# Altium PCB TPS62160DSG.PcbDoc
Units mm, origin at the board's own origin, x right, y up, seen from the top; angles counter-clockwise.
Board outline 13.43 x 12.66 mm, 2 copper layers (Top Layer, Bottom Layer); 1 components, 0 nets, 9 pads, 0 vias.
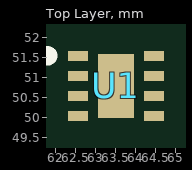
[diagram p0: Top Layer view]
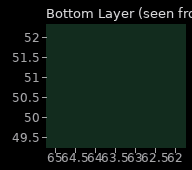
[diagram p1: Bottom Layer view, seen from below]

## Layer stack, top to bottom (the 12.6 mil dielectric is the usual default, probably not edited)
Top Layer: signal copper (thickness not stored)
Dielectric: dielectric 0.32, FR-4, Dk 4.8
Bottom Layer: signal copper (thickness not stored)

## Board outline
56.6,44.47 70.03,44.47 70.03,57.13 56.6,57.13

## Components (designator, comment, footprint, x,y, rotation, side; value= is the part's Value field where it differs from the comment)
U1 "TPS62160DSG" WSON-8_DSG0008A_2x2mm_P0.5mm_EP_NoOptionalVias 63.5,50.8 r0 top

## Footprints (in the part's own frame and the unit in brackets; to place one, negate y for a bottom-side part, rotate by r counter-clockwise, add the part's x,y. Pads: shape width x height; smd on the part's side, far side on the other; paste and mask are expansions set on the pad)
WSON-8_DSG0008A_2x2mm_P0.5mm_EP_NoOptionalVias [mm]
  rect 0.5x0.25 smd: 1(-0.95,0.75) 2(-0.95,0.25) 3(-0.95,-0.25) 4(-0.95,-0.75) 5(0.95,-0.75) 6(0.95,-0.25) 7(0.95,0.25) 8(0.95,0.75)
  rect 0.9x1.6 smd: 9(0,0)
  silkscreen extent -1.82,0.63 -1.58,0.87

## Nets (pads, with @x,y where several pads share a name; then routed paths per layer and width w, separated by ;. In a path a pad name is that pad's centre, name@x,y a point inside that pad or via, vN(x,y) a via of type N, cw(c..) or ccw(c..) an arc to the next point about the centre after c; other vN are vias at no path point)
pads on no net: U1.1 U1.2 U1.3 U1.4 U1.5 U1.6 U1.7 U1.8 U1.9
